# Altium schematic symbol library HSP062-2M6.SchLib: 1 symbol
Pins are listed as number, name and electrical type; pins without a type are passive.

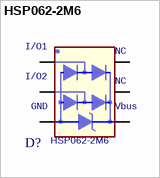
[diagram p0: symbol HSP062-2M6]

## HSP062-2M6
designator D?
footprint ST_QFN50P145X100X60-6L
pins: 1 I/O1, 2 I/O2, 3 GND, 4 Vbus, 5 NC1, 6 NC2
